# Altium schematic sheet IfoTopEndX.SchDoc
size A; DocumentNumber: 1; SheetNumber: 1; SheetTotal: 8; pInstance: Corner
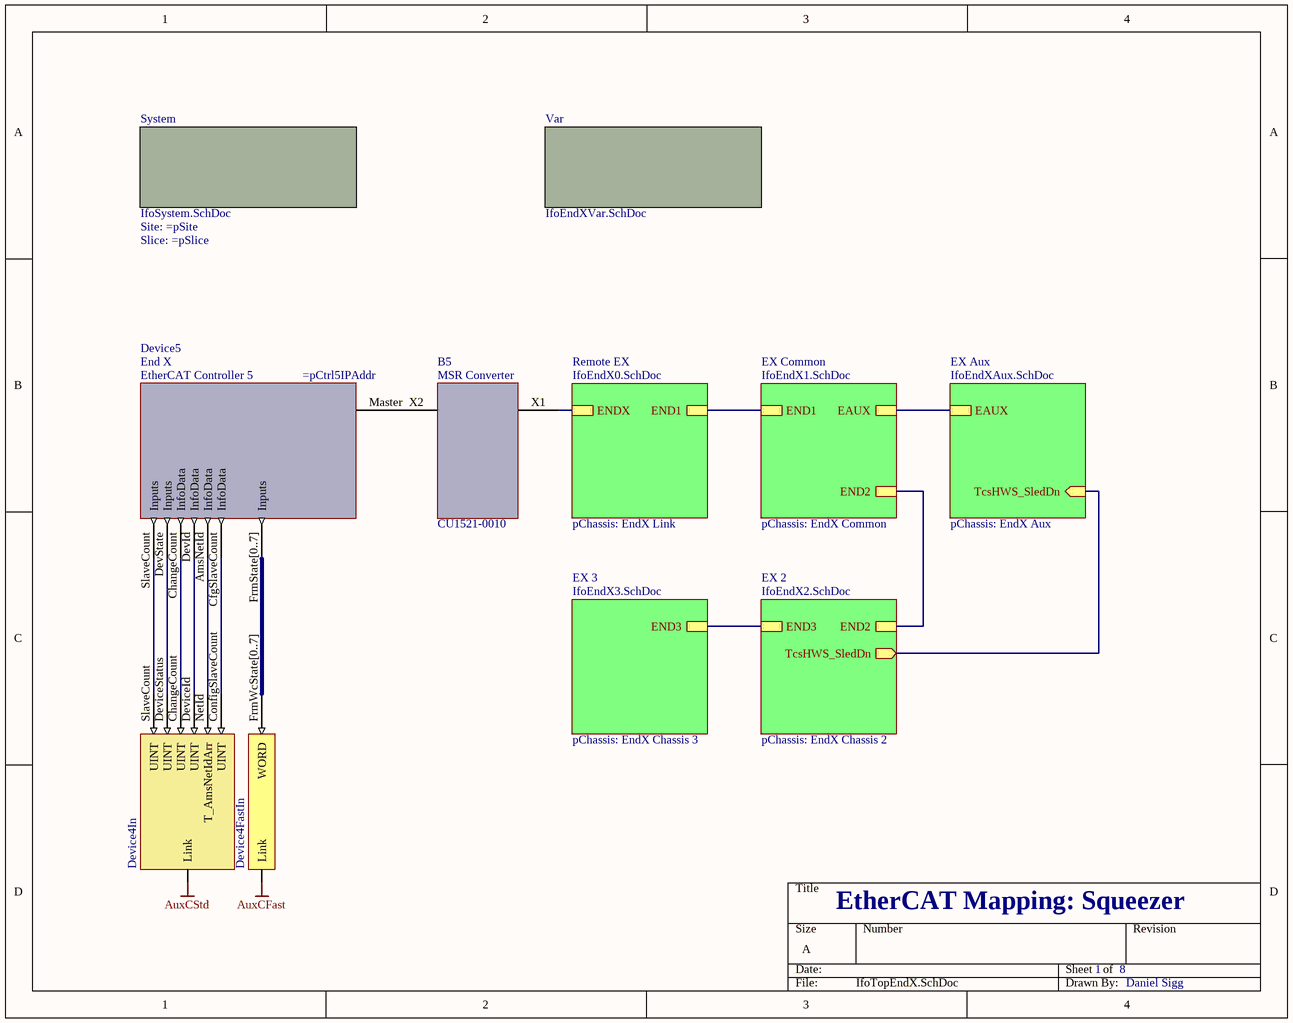
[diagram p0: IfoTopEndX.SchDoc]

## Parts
B5  MSR Converter  Part Number: CU1521-0010  (mechanical)
Device5  End X  DeviceDesc: EtherCAT Controller 5  (mechanical)
V91  Device4In  (no BOM)
V92  Device4FastIn  (no BOM)

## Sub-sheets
EX 2 = IfoEndX2.SchDoc: END2, END3, TcsHWS_SledDn (out)  | pChassis: EndX Chassis 2
EX 3 = IfoEndX3.SchDoc: END3  | pChassis: EndX Chassis 3
EX Aux = IfoEndXAux.SchDoc: EAUX, TcsHWS_SledDn (in)  | pChassis: EndX Aux
EX Common = IfoEndX1.SchDoc: END1, END2, EAUX  | pChassis: EndX Common
Remote EX = IfoEndX0.SchDoc: ENDX, END1  | pChassis: EndX Link
System = IfoSystem.SchDoc: no entries  | Site: =pSite; Slice: =pSlice
Var = IfoEndXVar.SchDoc: no entries

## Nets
AuxCFast: V92.?1(Link)
AuxCStd: V91.?1(Link)
NetB5_X1: B5.X1(B) ; sheet Remote EX/ENDX
NetB5_X2: B5.X2(A) Device5.Master(B)
NetDevice5_AmsNetId: Device5.AmsNetId(InfoData) V91.NetId(T_AmsNetIdArr)
NetDevice5_CfgSlaveCount: Device5.CfgSlaveCount(InfoData) V91.ConfigSlaveCount(UINT)
NetDevice5_ChangeCount: Device5.ChangeCount(InfoData) V91.ChangeCount(UINT)
NetDevice5_DevId: Device5.DevId(InfoData) V91.DeviceId(UINT)
NetDevice5_DevState: Device5.DevState(Inputs) V91.DeviceStatus(UINT)
NetDevice5_FrmState[0..7]: Device5.FrmState[0..7](Inputs) V92.FrmWcState[0..7](WORD)
NetDevice5_SlaveCount: Device5.SlaveCount(Inputs) V91.SlaveCount(UINT)
(unnamed): sheet Remote EX/END1, sheet EX Common/END1
(unnamed): sheet EX Common/END2, sheet EX 2/END2  [a separate net that carries the same name]
(unnamed): sheet EX Common/EAUX, sheet EX Aux/EAUX  [a separate net that carries the same name]
(unnamed): sheet EX 2/END3, sheet EX 3/END3  [a separate net that carries the same name]
(unnamed): sheet EX 2/TcsHWS_SledDn, sheet EX Aux/TcsHWS_SledDn  [a separate net that carries the same name]

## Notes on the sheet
- EtherCAT Mapping: Squeezer
- Daniel Sigg

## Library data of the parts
B5 = MediaConverterCAT5toFiber: EtherCAT Media Converter; BoxType: Box; BoxNextB: PMEMEWCT; BoxPrev: XAELCVIA; PortPrevFull: 1000/; Fullname: TIID^End X (EtherCAT)^MSR Converter (CU1521-0010); BoxAddr: 1001; Disabled: False
Device5 = EtherCATMaster: EtherCAT Master; Part Number: FC9022; DeviceData: 0001053F9908; BoxNextB: CLSUUFOZ; Fullname: TIID^End X (EtherCAT); BoxSubType: 111; Disabled: False
V91 = PLCInfo_MasterInfoInStruct: MasterInfoInStruct; PLC: H1AuxCorner; Task: AuxCStd; BoxType: Variable; Instance: H1AuxCorner Instance
V92 = PLCInfo_MasterInfoFastInStruct: MasterInfoFastInStruct; PLC: H1AuxCorner; Task: AuxCFast; BoxType: Variable; Instance: H1AuxCorner Instance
